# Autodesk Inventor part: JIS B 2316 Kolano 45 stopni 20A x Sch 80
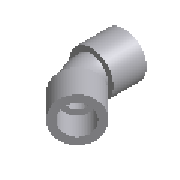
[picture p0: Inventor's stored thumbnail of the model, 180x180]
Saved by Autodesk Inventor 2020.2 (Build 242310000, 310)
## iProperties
Manager: www.cadconsulting.pl
Company: Fabian Stasiak CAD Consulting
IsCustomPart: 0
NAME: PIPING: JIS B 2316 45 Deg Elbow
DATA: <meta><inlinegroups number="0" deflen="0"></inlinegroups><connections number="2"></connections><angles><a>2.35619449019234</a></angles></meta>
Created: 2014-02
Part Number: JIS B 2316 Kolano 45 stopni 20A x Sch 80
Material: Stal
Description: Kolano
Document SubType Name: Modeling
Standard: JIS B 2316
Designer: F.Stasiak
Standards Organization: JIS
Language: pl-PL
Size Designation: 20A x Sch 80
Categories: <MemberInstance><Categories><Category DisplayName="Rury cienko- i grubościenne" InternalName="4347fa0f-2144-441d-94cd-e3e15c92b736" Mnemonic="TUBEANDPIPE"><Cate
Density: 1 g/cm^3
Appearance: Płyta
Catalog Web Link: www.expertbooks.pl
Author: F.Stasiak
Subject: Zbiór ćwiczeń. Autodesk Inventor 2020. Kurs Professional
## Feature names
1. Revolve1
2. Revolve2
3. Sweep1
## Parameters: S = 27.2 mm, D = 21.4 mm, T = 4.3 mm, C1 = 12.7 mm, G = 12.7 mm, d0 = 21.4 mm, d1 = 27.2 mm, d2 = 4.3 mm, d3 = 12.7 mm, d8 = 90 deg, d4 = 21.4 mm, d5 = 27.2 mm, d6 = 4.3 mm, d7 = 12.7 mm, d25 = 90 deg, d9 = 45 deg, d10 = 12.7 mm, d11 = 12.7 mm, d13 = 0, d37 = 0, Size_Designation = 12.345 mm
